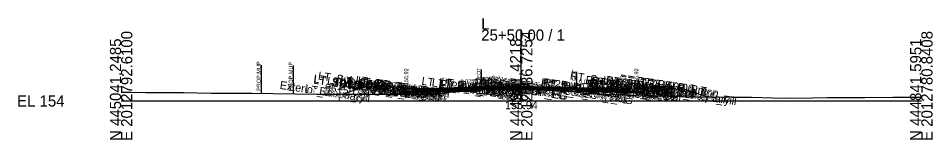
# Model space of a CAD drawing. Extents: x -26 to 4203, y -10 to 9526.
# Drawn here: x 974.3 to 1202.8, y 5490.3 to 5520.7 of the extents above; entities that cross this region are included whole.
import ezdxf

# ---------------------------------------------------------------- set-up
doc = ezdxf.new("R2010")
doc.units = 0
for name, color, linetype in [('Default', 7, 'Continuous'), ('Exist CMT Pavement', 7, 'Continuous'), ('Exist Cross Section Cell', 7, 'Continuous'), ('Exist XS Center Line Elevation Label', 7, 'Continuous'), ('Exist XS Ground Line', 7, 'Continuous'), ('Prop CMT Conc Surface', 7, 'Continuous'), ('Prop CMT Concrete Structures', 7, 'Continuous'), ('Prop CMT Pvmt Course 1', 7, 'Continuous'), ('Prop CMT Pvmt Course 1 CG', 7, 'Continuous'), ('Prop CMT Pvmt Course 1 Wedge', 7, 'Continuous'), ('Prop CMT Pvmt Course 2', 7, 'Continuous'), ('Prop CMT Pvmt Course 2 Wedge', 7, 'Continuous'), ('Prop CMT Pvmt Course 3', 7, 'Continuous'), ('Prop CMT Pvmt Course 3 Wedge', 7, 'Continuous'), ('Prop CMT Pvmt Surface', 7, 'Continuous'), ('Prop CMT Pvmt Wedge Surface 1', 7, 'Continuous'), ('Prop CMT Pvmt Wedge Surface 2', 7, 'Continuous'), ('Prop CMT Pvmt Wedge Surface 3', 7, 'Continuous'), ('Prop CMT Slope Grass', 7, 'Continuous'), ('Prop CMT Subgrade Earthwork', 7, 'Continuous'), ('Prop XS Hydro Elevations', 7, 'Continuous'), ('Prop XS Label Text', 7, 'Continuous'), ('Prop XS SE Text', 7, 'Continuous'), ('Prop XS Side Slope Text', 7, 'Continuous'), ('Scratch_Level_0', 7, 'Continuous')]:
    doc.layers.add(name, color=color, linetype=linetype)

msp = doc.modelspace()

# ---------------------------------------------------------------- linework, layer by layer
at = {"layer": 'Exist CMT Pavement'}
for points in [[(1100, 5502.94), (1099.14, 5502.93), (1098.89, 5502.93), (1096.44, 5502.9), (1096.36, 5502.9), (1095.06, 5502.9), (1093.87, 5502.89), (1093.8, 5502.89), (1091.34, 5502.84), (1090.89, 5502.83), (1090.01, 5502.82)], [(1100, 5502.94), (1100.53, 5502.94), (1101.14, 5502.93), (1101.35, 5502.93), (1101.74, 5502.91), (1103.87, 5502.81), (1104.42, 5502.79), (1106.36, 5502.72), (1107.06, 5502.67), (1108.85, 5502.57), (1109.72, 5502.53), (1111.39, 5502.46), (1112.79, 5502.37), (1113.82, 5502.3)]]:
    msp.add_lwpolyline(points, dxfattribs=at)
at = {"layer": 'Exist Cross Section Cell'}
for p, q in [((1100, 5500), (1100, 5517.86)), ((1000, 5500), (1100, 5500)), ((1100, 5500), (1200, 5500))]:
    msp.add_line(p, q, dxfattribs=at)
at = {"layer": 'Exist XS Ground Line'}
msp.add_lwpolyline([(1000, 5502.18), (1002.5, 5502.17), (1006.15, 5502.09), (1012.51, 5502.11), (1015.61, 5502.1), (1022.53, 5501.97), (1030.33, 5501.98), (1032.55, 5501.98), (1048.9, 5501.72), (1050.66, 5501.67), (1051.41, 5501.67), (1057.42, 5501.66), (1067.17, 5501.67), (1069.83, 5501.7), (1072.7, 5501.71), (1075.41, 5501.67), (1077.24, 5501.63), (1080.24, 5501.98), (1083.28, 5502.34), (1086.13, 5502.57), (1088.44, 5502.77), (1089.08, 5502.81), (1089.51, 5502.81), (1090.01, 5502.82), (1090.89, 5502.83), (1091.34, 5502.84), (1093.87, 5502.89), (1095.06, 5502.9), (1096.44, 5502.9), (1099.14, 5502.93), (1100, 5502.94), (1100.53, 5502.94), (1101.35, 5502.93), (1101.74, 5502.91), (1103.87, 5502.81), (1104.42, 5502.79), (1106.36, 5502.72), (1107.06, 5502.67), (1108.85, 5502.57), (1109.72, 5502.53), (1111.39, 5502.46), (1112.79, 5502.37), (1113.82, 5502.3), (1115.59, 5501.93), (1116.12, 5501.9), (1123.52, 5501.58), (1125.41, 5501.51), (1130.37, 5501.28), (1133.62, 5501.28), (1136.54, 5501.18), (1143.51, 5501.01), (1152.77, 5500.95), (1157.52, 5500.96), (1162.79, 5500.74), (1166.98, 5500.73), (1172.81, 5500.81), (1176.44, 5500.82), (1182.83, 5500.86), (1185.9, 5500.85), (1192.85, 5500.94), (1195.36, 5500.9), (1200, 5500.95)], dxfattribs=at)
at = {"layer": 'Prop CMT Conc Surface'}
for points in [[(1071.25, 5502.92), (1071.25, 5503.42), (1070.75, 5503.42)], [(1128.75, 5502.92), (1128.75, 5503.42), (1129.25, 5503.42)], [(1133.25, 5503.51), (1138.25, 5503.61)], [(1073.25, 5503.05), (1071.25, 5502.92)], [(1126.75, 5503.05), (1128.75, 5502.92)]]:
    msp.add_lwpolyline(points, dxfattribs=at)
at = {"layer": 'Prop CMT Concrete Structures'}
for points in [[(1073.25, 5503.05), (1071.25, 5502.92), (1071.25, 5503.42), (1070.75, 5503.42)], [(1070.75, 5503.42), (1070.75, 5502.41), (1073.25, 5502.47)], [(1102, 5503.67), (1101.99, 5503.84), (1101.24, 5504.09), (1100, 5504.11), (1098.76, 5504.09), (1098.01, 5503.84), (1098, 5503.67)], [(1098, 5503.67), (1100, 5503.72), (1102, 5503.67)], [(1126.75, 5503.05), (1128.75, 5502.92), (1128.75, 5503.42), (1129.25, 5503.42)], [(1129.25, 5503.42), (1129.25, 5502.41), (1126.75, 5502.47)], [(1138.25, 5503.61), (1133.25, 5503.51)], [(1133.25, 5503.51), (1133.25, 5503.18)], [(1133.25, 5503.18), (1138.25, 5503.28)], [(1138.25, 5503.28), (1138.25, 5503.61)], [(1073.25, 5502.47), (1073.25, 5503.05)], [(1126.75, 5502.47), (1126.75, 5503.05)]]:
    msp.add_lwpolyline(points, dxfattribs=at)
at = {"layer": 'Prop CMT Pvmt Course 1'}
for points in [[(1100, 5503.72), (1073.25, 5503.05)], [(1073.25, 5502.8), (1090.01, 5503.22)], [(1090.01, 5503.35), (1100, 5503.6)], [(1090.01, 5503.22), (1090.01, 5503.35)], [(1100, 5503.47), (1100, 5503.72)], [(1100, 5503.72), (1126.75, 5503.05)], [(1100, 5503.47), (1100, 5503.72)], [(1100, 5503.6), (1100, 5503.47), (1100, 5503.47)], [(1113.82, 5503.25), (1100, 5503.6)], [(1100, 5503.6), (1100, 5503.47), (1100, 5503.47)], [(1113.82, 5503.13), (1113.82, 5503.25)], [(1126.75, 5502.8), (1115.59, 5503.08)], [(1073.25, 5503.05), (1073.25, 5502.8)], [(1126.75, 5503.05), (1126.75, 5502.8)]]:
    msp.add_lwpolyline(points, dxfattribs=at)
at = {"layer": 'Prop CMT Pvmt Course 1 CG'}
for points in [[(1073.25, 5502.47), (1070.25, 5502.39), (1069.91, 5502.05)], [(1069.91, 5502.05), (1073.25, 5502.14)], [(1073.25, 5502.14), (1073.25, 5502.47)], [(1126.75, 5502.47), (1129.75, 5502.39), (1130.09, 5502.05)], [(1126.75, 5502.14), (1126.75, 5502.47)], [(1130.09, 5502.05), (1126.75, 5502.14)]]:
    msp.add_lwpolyline(points, dxfattribs=at)
at = {"layer": 'Prop CMT Pvmt Course 1 Wedge'}
for points in [[(1090.01, 5503.35), (1090.89, 5503.37), (1091.34, 5503.38), (1093.8, 5503.44), (1093.87, 5503.44), (1095.06, 5503.47), (1096.36, 5503.51), (1096.44, 5503.51), (1098.89, 5503.57), (1099.14, 5503.58), (1100, 5503.6)], [(1100, 5503.47), (1099.14, 5503.45), (1098.89, 5503.44), (1096.44, 5503.38), (1096.36, 5503.38), (1095.06, 5503.35), (1093.87, 5503.32), (1093.8, 5503.32), (1091.34, 5503.26), (1090.89, 5503.24), (1090.01, 5503.22)], [(1090.01, 5503.22), (1090.01, 5503.35)], [(1100, 5503.6), (1100, 5503.47)], [(1100, 5503.47), (1100, 5503.6)], [(1100, 5503.6), (1100.53, 5503.58), (1101.14, 5503.57), (1101.35, 5503.56), (1101.74, 5503.55), (1103.87, 5503.5), (1104.42, 5503.49), (1106.36, 5503.44), (1107.06, 5503.42), (1108.85, 5503.38), (1109.72, 5503.35), (1111.39, 5503.31), (1112.79, 5503.28), (1113.82, 5503.25)], [(1113.82, 5503.13), (1112.79, 5503.15), (1111.39, 5503.19), (1109.72, 5503.23), (1108.85, 5503.25), (1107.06, 5503.3), (1106.36, 5503.31), (1104.42, 5503.36), (1103.87, 5503.38), (1101.74, 5503.43), (1101.35, 5503.44), (1101.14, 5503.44), (1100.53, 5503.46), (1100, 5503.47)], [(1113.82, 5503.25), (1113.82, 5503.13)]]:
    msp.add_lwpolyline(points, dxfattribs=at)
at = {"layer": 'Prop CMT Pvmt Course 2'}
for points in [[(1090.01, 5503.22), (1073.25, 5502.8)], [(1090.01, 5502.89), (1090.01, 5503.22)], [(1113.82, 5502.79), (1113.82, 5503.13)], [(1115.59, 5503.08), (1126.75, 5502.8)], [(1073.25, 5502.47), (1090.01, 5502.89)], [(1073.25, 5502.8), (1073.25, 5502.47)], [(1126.75, 5502.47), (1115.59, 5502.75)], [(1126.75, 5502.8), (1126.75, 5502.47)]]:
    msp.add_lwpolyline(points, dxfattribs=at)
at = {"layer": 'Prop CMT Pvmt Course 2 Wedge'}
for points in [[(1090.01, 5503.22), (1090.89, 5503.24), (1091.34, 5503.26), (1093.8, 5503.32), (1093.87, 5503.32), (1095.06, 5503.35), (1096.36, 5503.38), (1096.44, 5503.38), (1098.89, 5503.44), (1099.14, 5503.45), (1100, 5503.47)], [(1090.01, 5502.89), (1090.01, 5503.22)], [(1100, 5503.14), (1099.14, 5503.12), (1098.89, 5503.11), (1096.44, 5503.05), (1096.36, 5503.05), (1095.06, 5503.02), (1093.87, 5502.99), (1093.8, 5502.98), (1091.34, 5502.92), (1090.89, 5502.91), (1090.01, 5502.89)], [(1100, 5503.47), (1100.53, 5503.46), (1101.14, 5503.44), (1101.35, 5503.44), (1101.74, 5503.43), (1103.87, 5503.38), (1104.42, 5503.36), (1106.36, 5503.31), (1107.06, 5503.3), (1108.85, 5503.25), (1109.72, 5503.23), (1111.39, 5503.19), (1112.79, 5503.15), (1113.82, 5503.13), (1115.49, 5503.08), (1115.57, 5503.08), (1115.59, 5503.08)], [(1100, 5503.14), (1100, 5503.47)], [(1100, 5503.47), (1100, 5503.14)], [(1115.59, 5502.75), (1115.57, 5502.75), (1115.49, 5502.75), (1113.82, 5502.79), (1112.79, 5502.82), (1111.39, 5502.85), (1109.72, 5502.9), (1108.85, 5502.92), (1107.06, 5502.96), (1106.36, 5502.98), (1104.42, 5503.03), (1103.87, 5503.04), (1101.74, 5503.1), (1101.35, 5503.1), (1101.14, 5503.11), (1100.53, 5503.13), (1100, 5503.14)], [(1113.82, 5503.13), (1113.82, 5502.79)]]:
    msp.add_lwpolyline(points, dxfattribs=at)
at = {"layer": 'Prop CMT Pvmt Course 3'}
for points in [[(1090.01, 5502.89), (1073.25, 5502.47)], [(1073.25, 5502.14), (1090.01, 5502.56)], [(1073.25, 5502.47), (1073.25, 5502.14)], [(1090.01, 5502.56), (1090.01, 5502.89)], [(1113.82, 5502.46), (1113.82, 5502.79)], [(1126.75, 5502.14), (1113.82, 5502.46)], [(1115.59, 5502.75), (1126.75, 5502.47)], [(1126.75, 5502.47), (1126.75, 5502.14)]]:
    msp.add_lwpolyline(points, dxfattribs=at)
at = {"layer": 'Prop CMT Pvmt Course 3 Wedge'}
for points in [[(1090.01, 5502.89), (1090.89, 5502.91), (1091.34, 5502.92), (1093.8, 5502.98), (1093.87, 5502.99), (1095.06, 5503.02), (1096.36, 5503.05), (1096.44, 5503.05), (1098.89, 5503.11), (1099.14, 5503.12), (1100, 5503.14)], [(1100, 5503.14), (1100.53, 5503.13), (1101.14, 5503.11), (1101.35, 5503.11), (1101.74, 5503.1), (1103.87, 5503.04), (1104.42, 5503.03), (1106.36, 5502.98), (1107.06, 5502.96), (1108.85, 5502.92), (1109.72, 5502.9), (1111.39, 5502.85), (1112.79, 5502.82), (1113.82, 5502.79), (1115.49, 5502.75), (1115.57, 5502.75), (1115.59, 5502.75)], [(1100, 5502.94), (1100, 5503.14)], [(1100, 5503.14), (1100, 5502.94)], [(1100, 5502.94), (1099.14, 5502.93), (1098.89, 5502.93), (1096.44, 5502.9), (1096.36, 5502.9), (1095.06, 5502.9), (1093.87, 5502.89), (1093.8, 5502.89), (1091.34, 5502.84), (1090.89, 5502.83), (1090.01, 5502.82)], [(1090.01, 5502.82), (1090.01, 5502.89)], [(1115.59, 5501.93), (1115.57, 5501.93), (1115.49, 5501.94), (1113.82, 5502.3), (1112.79, 5502.37), (1111.39, 5502.46), (1109.72, 5502.53), (1108.85, 5502.57), (1107.06, 5502.67), (1106.36, 5502.72), (1104.42, 5502.79), (1103.87, 5502.81), (1101.74, 5502.91), (1101.35, 5502.93), (1101.14, 5502.93), (1100.53, 5502.94), (1100, 5502.94)], [(1113.82, 5502.79), (1113.82, 5502.3)]]:
    msp.add_lwpolyline(points, dxfattribs=at)
at = {"layer": 'Prop CMT Pvmt Surface'}
for points in [[(1100, 5503.72), (1073.25, 5503.05)], [(1100, 5503.72), (1126.75, 5503.05)]]:
    msp.add_lwpolyline(points, dxfattribs=at)
at = {"layer": 'Prop CMT Pvmt Wedge Surface 1'}
for points in [[(1090.01, 5503.22), (1073.25, 5502.8)], [(1100, 5503.6), (1090.01, 5503.35)], [(1090.01, 5503.35), (1090.01, 5503.22)], [(1100, 5503.6), (1113.82, 5503.25)], [(1113.82, 5503.25), (1113.82, 5503.13)], [(1115.59, 5503.08), (1126.75, 5502.8)], [(1073.25, 5502.8), (1073.25, 5503.05)], [(1126.75, 5502.8), (1126.75, 5503.05)]]:
    msp.add_lwpolyline(points, dxfattribs=at)
at = {"layer": 'Prop CMT Pvmt Wedge Surface 2'}
for points in [[(1100, 5503.47), (1073.25, 5502.8)], [(1100, 5503.47), (1126.75, 5502.8)], [(1073.25, 5502.8), (1073.25, 5503.05)], [(1126.75, 5502.8), (1126.75, 5503.05)]]:
    msp.add_lwpolyline(points, dxfattribs=at)
at = {"layer": 'Prop CMT Pvmt Wedge Surface 3'}
for points in [[(1100, 5503.14), (1073.25, 5502.47)], [(1100, 5503.14), (1126.75, 5502.47)], [(1073.25, 5502.47), (1073.25, 5503.05)], [(1126.75, 5502.47), (1126.75, 5503.05)]]:
    msp.add_lwpolyline(points, dxfattribs=at)
at = {"layer": 'Prop CMT Slope Grass'}
for points in [[(1070.75, 5503.42), (1061.25, 5503.61), (1055.4, 5501.66)], [(1129.25, 5503.42), (1138.75, 5503.61), (1146.62, 5500.99)]]:
    msp.add_lwpolyline(points, dxfattribs=at)
at = {"layer": 'Prop CMT Subgrade Earthwork'}
for points in [[(1073.25, 5502.14), (1069.91, 5502.05), (1068.49, 5503.47)], [(1126.75, 5502.14), (1130.09, 5502.05), (1131.51, 5503.47)], [(1090.01, 5502.56), (1073.25, 5502.14)], [(1090.01, 5502.56), (1090.03, 5502.82)], [(1113.82, 5502.46), (1126.75, 5502.14)], [(1113.82, 5502.46), (1113.82, 5502.3)]]:
    msp.add_lwpolyline(points, dxfattribs=at)
at = {"layer": 'Prop XS Label Text'}
for p, q in [((1035, 5508.94), (1035, 5501.94)), ((1043, 5508.82), (1043, 5501.82)), ((1090.01, 5507.82), (1090.01, 5502.82)), ((1113.82, 5507.3), (1113.82, 5502.3))]:
    msp.add_line(p, q, dxfattribs=at)

# ---------------------------------------------------------------- texts
at = {"layer": 'Default'}
msp.add_text('-', height=0.0001, dxfattribs=at).set_placement((1000, 5500))
at = {"layer": 'Exist Cross Section Cell'}
for s, p in [('L', (1090, 5517.86)), ('25+50.00 / 1', (1090, 5515.06)), ('EL 154', (974, 5498.6))]:
    msp.add_text(s, height=2.8, dxfattribs=at).set_placement(p)
for s, p in [('E 2012792.6100', (1002.8, 5490)), ('E 2012786.7254', (1102.8, 5490)), ('E 2012780.8408', (1202.8, 5490)), ('N 445041.2485', (1000, 5490)), ('N 444941.4218', (1100, 5490)), ('N 444841.5951', (1200, 5490))]:
    msp.add_text(s, height=2.8, rotation=90, dxfattribs=at).set_placement(p)
at = {"layer": 'Exist XS Center Line Elevation Label'}
msp.add_text('156.94', height=2, dxfattribs=at).set_placement((1095.96, 5497.94))
at = {"layer": 'Prop XS Hydro Elevations'}
for p in [(1071.75, 5503.92), (1129.25, 5503.92)]:
    msp.add_text('156.92', height=1, rotation=90, dxfattribs=at).set_placement(p)
at = {"layer": 'Prop XS Label Text'}
for s, p in [('PROP.MUP', (1034.9, 5502.52)), ('PROP.MUP', (1042.9, 5502.39)), ('E. EOT', (1089.91, 5503.85)), ('E. EOT', (1113.72, 5503.33))]:
    msp.add_text(s, height=1, rotation=90, dxfattribs=at).set_placement(p)
at = {"layer": 'Prop XS SE Text'}
for rotation, p in [(1.4305, (1084.87, 5504.34)), (358.5695, (1114.47, 5504.38))]:
    msp.add_text('0.025', height=1, rotation=rotation, dxfattribs=at).set_placement(p)
at = {"layer": 'Prop XS Side Slope Text'}
for rotation, p in [(18.4376, (1057.33, 5503.1)), (341.5621, (1142.17, 5503.26))]:
    msp.add_text('3:1', height=1, rotation=rotation, dxfattribs=at).set_placement(p)
at = {"layer": 'Scratch_Level_0'}
for s, p in [('LT_SDWK_Out_Top', (1047.99, 5504.67)), ('LT_SDWK_Out_Bot', (1048.02, 5504.33)), ('LT_Sub_Trench_Out_DLT', (1049.13, 5505.36)), ('LT_CSLP_Pnt', (1051.38, 5504.08)), ('25+50.00', (1054.64, 5503.63)), ('LT_SDWK_In_Top', (1054.59, 5504.33)), ('LT_SDWK_In_Bot', (1054.63, 5503.99)), ('LT_CG_Top_Face', (1058.5, 5504.32)), ('LT_CG_Top_BOC', (1059.01, 5504.17)), ('LT_CG_Top_Gut', (1059.47, 5503.68)), ('25+50.00', (1063.03, 5503.45)), ('LT_PV1_OEOT', (1063.94, 5503.44)), ('25+50.00', (1064.17, 5503.44)), ('LT_PV_Sub_Tie_Out', (1074.99, 5504.07)), ('LT_PV_OEEOP_EG', (1077.54, 5503.68)), ('LT_PV2_OEEOP', (1079.29, 5503.82)), ('LT_PV3_OEEOP', (1079.29, 5503.49)), ('LT_PV1_OEEOP', (1079.85, 5503.86)), ('25+50.00', (1087.71, 5503.6)), ('RT_PV_IEEOP_EG', (1088.12, 5503.71)), ('LT_PV_IEEOP_EG', (1088.17, 5503.7)), ('MI_Face In', (1089.84, 5504.05)), ('RT_PV2_IEEOP', (1089.87, 5503.98)), ('RT_PV3_IEEOP', (1089.87, 5503.65)), ('LT_PV2_IEEOP', (1089.92, 5503.97)), ('LT_PV3_IEEOP', (1089.92, 5503.64)), ('RT_PV1_IEEOP', (1090.43, 5504.02)), ('LT_PV1_IEEOP', (1090.48, 5504.01)), ('MI_Bot In', (1090.81, 5503.74)), ('25+50.00', (1091.17, 5503.71)), ('25+50.00', (1091.6, 5503.99)), ('MI_Top In', (1091.54, 5504.16)), ('MI_Face Out', (1092.22, 5504.29)), ('MI_Top Out', (1092.42, 5504.4)), ('MI_Crown', (1093, 5504.15)), ('MI_Bot Out', (1093.21, 5503.98)), ('PV1_PGL', (1094.39, 5503.55)), ('25+50.00', (1095.17, 5503.77)), ('MI_Bot', (1095.09, 5503.45)), ('RT_PV2_OEEOP', (1104.82, 5503.69)), ('RT_PV1_OEEOP', (1105.38, 5503.73)), ('RT_Sub_Trench_Out_DLT', (1112.09, 5505.37)), ('RT_CG_Top_Face', (1115.96, 5504.33)), ('RT_CG1_Shelf_Out', (1116.26, 5503.41)), ('RT_CG_Top_Gut', (1116.92, 5503.69)), ('RT_PV1_OEOT', (1117.4, 5503.45)), ('RT_CG_Top_BOC', (1117.47, 5504.18)), ('RT_SDWK_In_Top', (1121.05, 5504.33)), ('RT_SDWK_In_Bot', (1121.08, 5503.99)), ('25+50.00', (1122.35, 5503.44)), ('RT_SDWK_Out_Top', (1124.44, 5504.67)), ('RT_SDWK_Out_Bot', (1124.47, 5504.34)), ('25+50.00', (1125.67, 5503.51)), ('RT_CSLP_Pnt', (1128.84, 5504.09)), ('25+50.00', (1131.85, 5503.63)), ('Exterior Boundary', (1039.57, 5503.03)), ('LT_Slope_Fill', (1045.87, 5502.08)), ('25+50.00', (1050.8, 5502.42)), ('LT_CG1_Shelf_Out', (1056.8, 5503.4)), ('LT_CG_Bot_BOC', (1059.05, 5503.15)), ('LT_Sub_OEOP', (1059.98, 5502.53)), ('LT_CG_Bot_IE', (1063.13, 5502.98)), ('LT_Sub_OEOT', (1063.29, 5502.62)), ('LT_PV2_OEOT', (1063.38, 5503.27)), ('LT_PV3_OEOT', (1063.38, 5502.94)), ('25+50.00', (1065.06, 5502.98)), ('LT_Sub_OEEOP', (1079.2, 5503.17)), ('PV2_PGL', (1093.82, 5503.39)), ('RT_PV_Sub_Tie_Out', (1100.5, 5503.18)), ('RT_PV_OEEOP_EG', (1103.08, 5502.79)), ('RT_Sub_OEEOP', (1104.73, 5503.03)), ('RT_PV3_OEEOP', (1104.82, 5503.35)), ('25+50.00', (1108.23, 5503.36)), ('RT_CG_Bot_IE', (1116.58, 5502.98)), ('RT_Sub_OEOT', (1116.74, 5502.63)), ('RT_PV2_OEOT', (1116.84, 5503.28)), ('RT_PV3_OEOT', (1116.84, 5502.95)), ('RT_CG_Bot_BOC', (1117.5, 5503.16)), ('RT_Sub_OEOP', (1120.12, 5502.54)), ('25+50.00', (1120.73, 5503.01)), ('Exterior Boundary', (1130.79, 5502.35)), ('RT_Slope_Fill', (1137.05, 5501.42))]:
    msp.add_text(s, height=2, rotation=351.4697, dxfattribs=at).set_placement(p)

doc.saveas('drawing.dxf')
